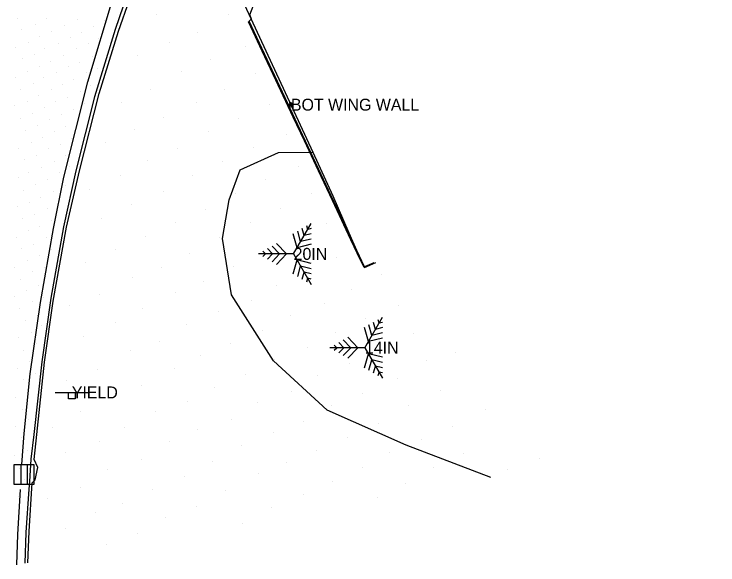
# Model space of a CAD drawing. Extents: x 1729983 to 1730242, y 468641 to 469019.
# Drawn here: x 1730093.6 to 1730200, y 468641.1 to 468724.3 of the extents above; entities that cross this region are included whole.
import ezdxf

# ---------------------------------------------------------------- set-up
doc = ezdxf.new("R2010")
doc.units = 0
for name, color, linetype in [('Default', 7, 'Continuous'), ('S_Bridge_Abutment_Bottom', 7, 'Continuous'), ('S_Bridge_Wingwall', 7, 'Continuous'), ('S_Curb_Type_1', 7, 'Continuous'), ('S_Drainage_CB', 7, 'Continuous'), ('S_Ground_LevelString', 7, 'Continuous'), ('S_Ground_SpotElevation', 7, 'Continuous'), ('S_Misc_MiscFeature', 7, 'Continuous'), ('S_Misc_MiscItems', 7, 'Continuous'), ('S_Roadway_Edge_Pavement', 7, 'Continuous'), ('S_Roadway_Painted_Lines', 7, 'Continuous'), ('S_Text', 7, 'Continuous'), ('S_Traffic_Sign_SinglePost', 7, 'Continuous'), ('S_Trees_Bush_Line', 7, 'Continuous'), ('S_Trees_Conifer_Pay', 7, 'Continuous')]:
    doc.layers.add(name, color=color, linetype=linetype)

# ---------------------------------------------------------------- blocks, each defined once
blk = doc.blocks.new('POINT_DISPLAY')
at = {"layer": 'Default'}
blk.add_line((0, 0), (0, 0), dxfattribs=at)

msp = doc.modelspace()

# ---------------------------------------------------------------- linework, layer by layer
at = {"layer": 'S_Bridge_Abutment_Bottom'}
msp.add_lwpolyline([(1730181.43, 468864.71), (1730176.51, 468862.35), (1730175.43, 468859.5), (1730170.12, 468844.95), (1730162.58, 468824.38), (1730156.01, 468806.68), (1730146.89, 468781.99), (1730136.8, 468754.6), (1730127.19, 468728.47), (1730129.43, 468723.65)], dxfattribs=at)
at = {"layer": 'S_Bridge_Wingwall'}
msp.add_lwpolyline([(1730148.03, 468686.77), (1730146.59, 468686.15), (1730129.16, 468723.27)], dxfattribs=at)
at = {"layer": 'S_Curb_Type_1'}
msp.add_lwpolyline([(1730095.69, 468641.41), (1730095.91, 468646.14), (1730096.35, 468653.52), (1730096.82, 468653.99), (1730097.2, 468655.85), (1730096.66, 468657.04), (1730097.06, 468660.8), (1730098.24, 468671.76), (1730099.53, 468680.95), (1730101.56, 468692.14), (1730103.52, 468700.63), (1730106.5, 468712.33), (1730109.42, 468721.77), (1730114.4, 468736), (1730118.96, 468748.43), (1730124.35, 468762.75), (1730131.22, 468781.92), (1730136.35, 468795.8), (1730142.85, 468813.48), (1730149.85, 468832.5), (1730156.77, 468851.57), (1730163.43, 468869.4), (1730166.7, 468878.04), (1730172.48, 468894.17)], dxfattribs=at)
at = {"layer": 'S_Drainage_CB'}
for p, q in [((1730094.62, 468656.28), (1730094.62, 468653.28)), ((1730095.62, 468656.28), (1730095.62, 468653.28))]:
    msp.add_line(p, q, dxfattribs=at)
msp.add_lwpolyline([(1730093.62, 468656.28), (1730096.62, 468656.28), (1730096.62, 468653.28), (1730093.62, 468653.28)], close=True, dxfattribs=at)
at = {"layer": 'S_Ground_LevelString'}
msp.add_lwpolyline([(1730129.02, 468723.21), (1730131.1, 468718.79), (1730133.17, 468714.4), (1730135.79, 468708.82), (1730137.47, 468705.24), (1730139.6, 468700.72), (1730141.73, 468696.2), (1730144.51, 468690.29), (1730145.46, 468688.27), (1730146.49, 468686.07)], dxfattribs=at)
at = {"layer": 'S_Misc_MiscFeature'}
for points in [[(1730129.16, 468723.27), (1730129.52, 468723.61), (1730129.27, 468724.21), (1730130.13, 468726.5)], [(1730129.43, 468723.65), (1730136.9, 468707.6), (1730138.79, 468703.46), (1730141.8, 468696.85), (1730144.21, 468691.28), (1730145.74, 468687.85), (1730146.59, 468686.03), (1730148.32, 468686.8)]]:
    msp.add_lwpolyline(points, dxfattribs=at)
at = {"layer": 'S_Misc_MiscItems'}
for p, q in [((1730135.48, 468711.04), (1730135.48, 468710.25)), ((1730135.88, 468710.64), (1730135.09, 468710.64)), ((1730135.75, 468710.38), (1730135.22, 468710.91)), ((1730135.75, 468710.91), (1730135.22, 468710.38))]:
    msp.add_line(p, q, dxfattribs=at)
at = {"layer": 'S_Roadway_Edge_Pavement'}
msp.add_lwpolyline([(1730169.44, 468886.97), (1730164.5, 468873.71), (1730156.5, 468852.01), (1730147.72, 468828.28), (1730138.37, 468802.61), (1730128.94, 468777.01), (1730117.48, 468745.73), (1730111.87, 468730.71), (1730108.89, 468721.99), (1730105.79, 468711.83), (1730102.94, 468700.65), (1730101.12, 468692.18), (1730099.16, 468681.42), (1730097.82, 468671.81), (1730096.59, 468660.81), (1730096.17, 468657.1), (1730095.96, 468653.71), (1730095.87, 468652.57), (1730095.42, 468646.03), (1730095.25, 468641.37)], dxfattribs=at)
at = {"layer": 'S_Roadway_Painted_Lines'}
for points in [[(1730094.8, 468656.26), (1730095.17, 468660.96), (1730096.08, 468669.98), (1730097.64, 468680.77), (1730099.58, 468691.95), (1730101.13, 468699.69), (1730104.77, 468714.07), (1730108.65, 468727.01), (1730112.54, 468738.83), (1730119.79, 468759.43), (1730137.2, 468807.81), (1730148.9, 468839.72), (1730160.49, 468871.27), (1730175.8, 468912.85), (1730190.41, 468952.88), (1730200.04, 468978.35)], [(1730094.05, 468641.11), (1730094.18, 468645.69), (1730094.57, 468652.49)]]:
    msp.add_lwpolyline(points, dxfattribs=at)
at = {"layer": 'S_Traffic_Sign_SinglePost'}
msp.add_line((1730099.86, 468667.18), (1730104.85, 468667.18), dxfattribs=at)
msp.add_lwpolyline([(1730101.85, 468667.18), (1730102.85, 468667.18), (1730102.85, 468666.18), (1730101.85, 468666.18)], close=True, dxfattribs=at)
at = {"layer": 'S_Trees_Bush_Line'}
msp.add_lwpolyline([(1730165.71, 468654.31), (1730152.92, 468659.18), (1730140.95, 468664.48), (1730132.83, 468671.92), (1730126.5, 468681.91), (1730125.15, 468690.44), (1730126.12, 468696.26), (1730127.8, 468700.8), (1730133.58, 468703.44), (1730138.79, 468703.46)], dxfattribs=at)
at = {"layer": 'S_Trees_Conifer_Pay'}
for p, q in [((1730135.89, 468688.1), (1730138.55, 468692.71)), ((1730137.48, 468690.87), (1730137.18, 468691.92)), ((1730138.02, 468691.79), (1730137.86, 468692.32)), ((1730138.55, 468691.92), (1730138.02, 468691.79)), ((1730136.42, 468689.03), (1730135.81, 468691.13)), ((1730136.95, 468689.95), (1730136.5, 468691.53)), ((1730138.55, 468691.13), (1730137.48, 468690.87)), ((1730134.82, 468688.1), (1730133.3, 468689.69)), ((1730138.55, 468690.34), (1730136.95, 468689.95)), ((1730132.69, 468688.1), (1730131.93, 468688.89)), ((1730133.76, 468688.1), (1730132.62, 468689.29)), ((1730138.55, 468689.55), (1730136.42, 468689.03)), ((1730135.89, 468688.1), (1730130.56, 468688.1)), ((1730131.63, 468688.1), (1730131.25, 468688.5)), ((1730131.25, 468687.71), (1730131.63, 468688.1)), ((1730131.93, 468687.31), (1730132.69, 468688.1)), ((1730132.62, 468686.92), (1730133.76, 468688.1)), ((1730133.3, 468686.52), (1730134.82, 468688.1)), ((1730135.89, 468688.1), (1730138.55, 468683.49)), ((1730135.81, 468685.08), (1730136.42, 468687.18)), ((1730138.55, 468686.65), (1730136.42, 468687.18)), ((1730136.5, 468684.68), (1730136.95, 468686.26)), ((1730138.55, 468685.86), (1730136.95, 468686.26)), ((1730137.18, 468684.28), (1730137.48, 468685.34)), ((1730138.55, 468685.08), (1730137.48, 468685.34)), ((1730137.86, 468683.89), (1730138.02, 468684.42)), ((1730138.55, 468684.28), (1730138.02, 468684.42)), ((1730146.67, 468673.93), (1730149.33, 468678.54)), ((1730148.8, 468677.62), (1730148.65, 468678.15)), ((1730147.2, 468674.86), (1730146.59, 468676.96)), ((1730147.73, 468675.78), (1730147.28, 468677.36)), ((1730148.26, 468676.7), (1730147.96, 468677.75)), ((1730149.33, 468676.96), (1730148.26, 468676.7)), ((1730149.33, 468677.75), (1730148.8, 468677.62)), ((1730149.33, 468676.17), (1730147.73, 468675.78)), ((1730144.54, 468673.93), (1730143.4, 468675.12)), ((1730145.6, 468673.93), (1730144.08, 468675.51)), ((1730149.33, 468675.38), (1730147.2, 468674.86)), ((1730146.67, 468673.93), (1730141.34, 468673.93)), ((1730142.41, 468673.93), (1730142.03, 468674.33)), ((1730142.03, 468673.54), (1730142.41, 468673.93)), ((1730143.47, 468673.93), (1730142.71, 468674.72)), ((1730142.71, 468673.14), (1730143.47, 468673.93)), ((1730143.4, 468672.74), (1730144.54, 468673.93)), ((1730144.08, 468672.35), (1730145.6, 468673.93)), ((1730146.67, 468673.93), (1730149.33, 468669.32)), ((1730146.59, 468670.9), (1730147.2, 468673.01)), ((1730149.33, 468672.48), (1730147.2, 468673.01)), ((1730147.28, 468670.51), (1730147.73, 468672.09)), ((1730149.33, 468671.69), (1730147.73, 468672.09)), ((1730147.96, 468670.11), (1730148.26, 468671.16)), ((1730149.33, 468670.9), (1730148.26, 468671.16)), ((1730148.65, 468669.72), (1730148.8, 468670.24)), ((1730149.33, 468670.11), (1730148.8, 468670.24))]:
    msp.add_line(p, q, dxfattribs=at)

# ---------------------------------------------------------------- block references
at = {"layer": 'S_Ground_SpotElevation'}
for p in [(1730115.12, 468724.31), (1730125.99, 468724.21), (1730094.13, 468723.63), (1730096.81, 468722.74), (1730098.57, 468723.67), (1730103.15, 468723.56), (1730107.34, 468723.36), (1730094.72, 468721.99), (1730099.25, 468721.68), (1730101.32, 468722.66), (1730105.67, 468722.4), (1730097.47, 468720.95), (1730102.18, 468720.82), (1730103.76, 468721.54), (1730106.37, 468720.59), (1730121.36, 468721.58), (1730095.75, 468720.02), (1730100.28, 468719.89), (1730104.81, 468719.86), (1730117.14, 468719.96), (1730093.78, 468719.23), (1730098.19, 468719.11), (1730103.02, 468719.07), (1730128.57, 468719.45), (1730094.89, 468717.56), (1730096.65, 468718.2), (1730101.14, 468718.07), (1730105.47, 468717.95), (1730112.24, 468718.11), (1730123.26, 468717.4), (1730097.49, 468716.46), (1730099.13, 468717.23), (1730101.91, 468716.35), (1730103.54, 468717.07), (1730095.64, 468715.69), (1730100.11, 468715.52), (1730104.52, 468715.45), (1730106.17, 468716.18), (1730118.86, 468715.62), (1730130.13, 468715.28), (1730093.77, 468714.68), (1730098.12, 468714.76), (1730102.66, 468714.48), (1730096.53, 468713.85), (1730100.99, 468713.7), (1730105.21, 468713.52), (1730094.64, 468712.88), (1730097.36, 468712.07), (1730099.21, 468712.91), (1730103.66, 468712.7), (1730114.27, 468712.98), (1730125.48, 468712.94), (1730095.6, 468711.17), (1730099.9, 468711.06), (1730101.76, 468711.74), (1730109.85, 468710.97), (1730121.26, 468711.04), (1730093.73, 468710.44), (1730098.23, 468710.15), (1730102.59, 468709.96), (1730104.25, 468710.82), (1730132.21, 468710.65), (1730096.41, 468709.38), (1730100.79, 468709.09), (1730094.55, 468708.52), (1730099.05, 468708.45), (1730103.35, 468708.24), (1730116.24, 468708.7), (1730127.58, 468708.61), (1730097.13, 468707.44), (1730101.46, 468707.34), (1730111.89, 468706.93), (1730095.41, 468706.7), (1730097.99, 468705.65), (1730099.81, 468706.62), (1730123.08, 468706.55), (1730134.74, 468706.18), (1730096.24, 468704.99), (1730100.65, 468704.68), (1730102.31, 468705.48), (1730107.39, 468704.87), (1730094.33, 468703.99), (1730098.9, 468704.02), (1730118.38, 468704), (1730129.83, 468704.13), (1730097.06, 468703.03), (1730101.33, 468702.92), (1730095.18, 468702.35), (1730099.69, 468702.06), (1730113.86, 468702.26), (1730125.13, 468702.06), (1730095.78, 468700.38), (1730097.78, 468701.13), (1730100.51, 468700.34), (1730102.07, 468701.25), (1730136.7, 468701.37), (1730094.25, 468699.68), (1730098.75, 468699.4), (1730109.76, 468699.93), (1730120.57, 468699.94), (1730131.58, 468699.31), (1730096.9, 468698.59), (1730101.35, 468698.36), (1730095, 468697.63), (1730099.52, 468697.52), (1730105.04, 468697.82), (1730116.26, 468697.45), (1730127.05, 468697.24), (1730138.64, 468697.19), (1730097.6, 468696.67), (1730094.16, 468695.27), (1730095.95, 468695.92), (1730100.37, 468695.75), (1730111.35, 468695.5), (1730096.71, 468694.01), (1730098.65, 468694.99), (1730122.52, 468694.86), (1730133.88, 468694.97), (1730094.84, 468693.44), (1730099.32, 468693.19), (1730106.77, 468693.43), (1730097.51, 468692.19), (1730117.98, 468692.83), (1730129.44, 468692.86), (1730140.79, 468692.65), (1730095.84, 468691.59), (1730113.46, 468690.77), (1730093.94, 468690.57), (1730098.45, 468690.52), (1730124.7, 468690.54), (1730135.86, 468690.42), (1730094.67, 468688.85), (1730096.5, 468689.58), (1730099.3, 468688.69), (1730109.03, 468688.72), (1730097.45, 468687.8), (1730120.18, 468688.15), (1730131.34, 468688.33), (1730142.43, 468687.56), (1730095.64, 468687.03), (1730104.4, 468686.77), (1730093.76, 468686.06), (1730098.27, 468685.99), (1730115.85, 468686.02), (1730126.73, 468686.12), (1730137.85, 468685.53), (1730096.43, 468685.38), (1730111.58, 468684.48), (1730149.13, 468684.96), (1730094.63, 468684.27), (1730097.24, 468683.32), (1730122.29, 468683.99), (1730133.33, 468683.3), (1730095.51, 468682.61), (1730144.69, 468682.72), (1730093.64, 468681.63), (1730098.05, 468681.46), (1730106.52, 468681.89), (1730117.96, 468682.22), (1730096.36, 468680.85), (1730102.04, 468680.25), (1730129.59, 468681.09), (1730140.62, 468680.62), (1730151.71, 468680.34), (1730094.49, 468679.92), (1730113.11, 468679.81), (1730124.47, 468679.39), (1730095.37, 468678.03), (1730097.09, 468678.86), (1730135.47, 468678.8), (1730146.69, 468678.29), (1730097.78, 468677.27), (1730108.98, 468677.76), (1730119.74, 468677.37), (1730096.22, 468676.25), (1730131.19, 468676.48), (1730142.16, 468676.23), (1730154.01, 468676.02), (1730094.27, 468675.51), (1730104.05, 468675.57), (1730115.6, 468674.79), (1730097.04, 468674.49), (1730126.4, 468674.5), (1730137.97, 468673.95), (1730095.11, 468673.48), (1730111.24, 468673.44), (1730121.79, 468672.79), (1730149.01, 468673.56), (1730160.34, 468673.24), (1730096, 468671.79), (1730132.97, 468672.18), (1730156.01, 468672.01), (1730094.2, 468670.85), (1730106.22, 468670.68), (1730117.86, 468670.83), (1730144.29, 468671.59), (1730096.79, 468670.06), (1730128.57, 468669.89), (1730139.56, 468669.8), (1730095, 468669.09), (1730101.48, 468668.91), (1730151.56, 468669.28), (1730095.87, 468667.42), (1730112.92, 468668.15), (1730123.94, 468667.84), (1730158.14, 468667.39), (1730093.91, 468666.4), (1730108.5, 468666.37), (1730135.6, 468667.33), (1730146.36, 468667.07), (1730119.83, 468665.77), (1730130.47, 468665.61), (1730153.29, 468665.24), (1730094.9, 468664.63), (1730103.69, 468664.22), (1730114.99, 468664.29), (1730141.68, 468665.15), (1730164.88, 468664.53), (1730126.48, 468663.14), (1730095.74, 468663.01), (1730137.33, 468662.84), (1730148.68, 468662.4), (1730159.85, 468662.02), (1730093.86, 468662), (1730099.41, 468661.86), (1730110.28, 468661.82), (1730121.41, 468661.53), (1730132.89, 468661.15), (1730094.73, 468660.35), (1730144.03, 468660.38), (1730155.17, 468659.99), (1730106.47, 468659.74), (1730117.05, 468659.71), (1730128.06, 468659.17), (1730095.59, 468658.33), (1730101.44, 468658.09), (1730139.4, 468658.35), (1730150.45, 468658.12), (1730161.58, 468657.93), (1730093.65, 468657.65), (1730112.94, 468657.06), (1730123.57, 468656.72), (1730173.01, 468657.23), (1730134.76, 468656.54), (1730146.33, 468655.87), (1730157.01, 468655.76), (1730094.49, 468655.61), (1730107.8, 468655.5), (1730130.59, 468654.98), (1730168.29, 468655.54), (1730095.21, 468654.03), (1730119.38, 468654.53), (1730141.7, 468653.71), (1730103.68, 468652.8), (1730114.59, 468652.44), (1730152.73, 468653.35), (1730094.33, 468651.38), (1730125.61, 468652.36), (1730137.36, 468651.77), (1730098.74, 468651.11), (1730109.99, 468650.44), (1730148.62, 468651.29), (1730121.15, 468649.99), (1730132.54, 468649.75), (1730105.86, 468649.07), (1730116.47, 468648.27), (1730128.12, 468647.43), (1730094.29, 468646.8), (1730101.44, 468646.66), (1730112.32, 468645.79), (1730107.56, 468644.24), (1730094.02, 468642.57)]:
    msp.add_blockref('POINT_DISPLAY', p, dxfattribs=at)

# ---------------------------------------------------------------- texts
at = {"layer": 'S_Text'}
for s, p in [('BOT WING WALL', (1730135.48, 468709.74)), ('20IN', (1730135.89, 468687.2)), ('14IN', (1730146.67, 468673.03)), ('YIELD', (1730102.35, 468666.27))]:
    msp.add_text(s, height=1.8, dxfattribs=at).set_placement(p)

doc.saveas('drawing.dxf')
